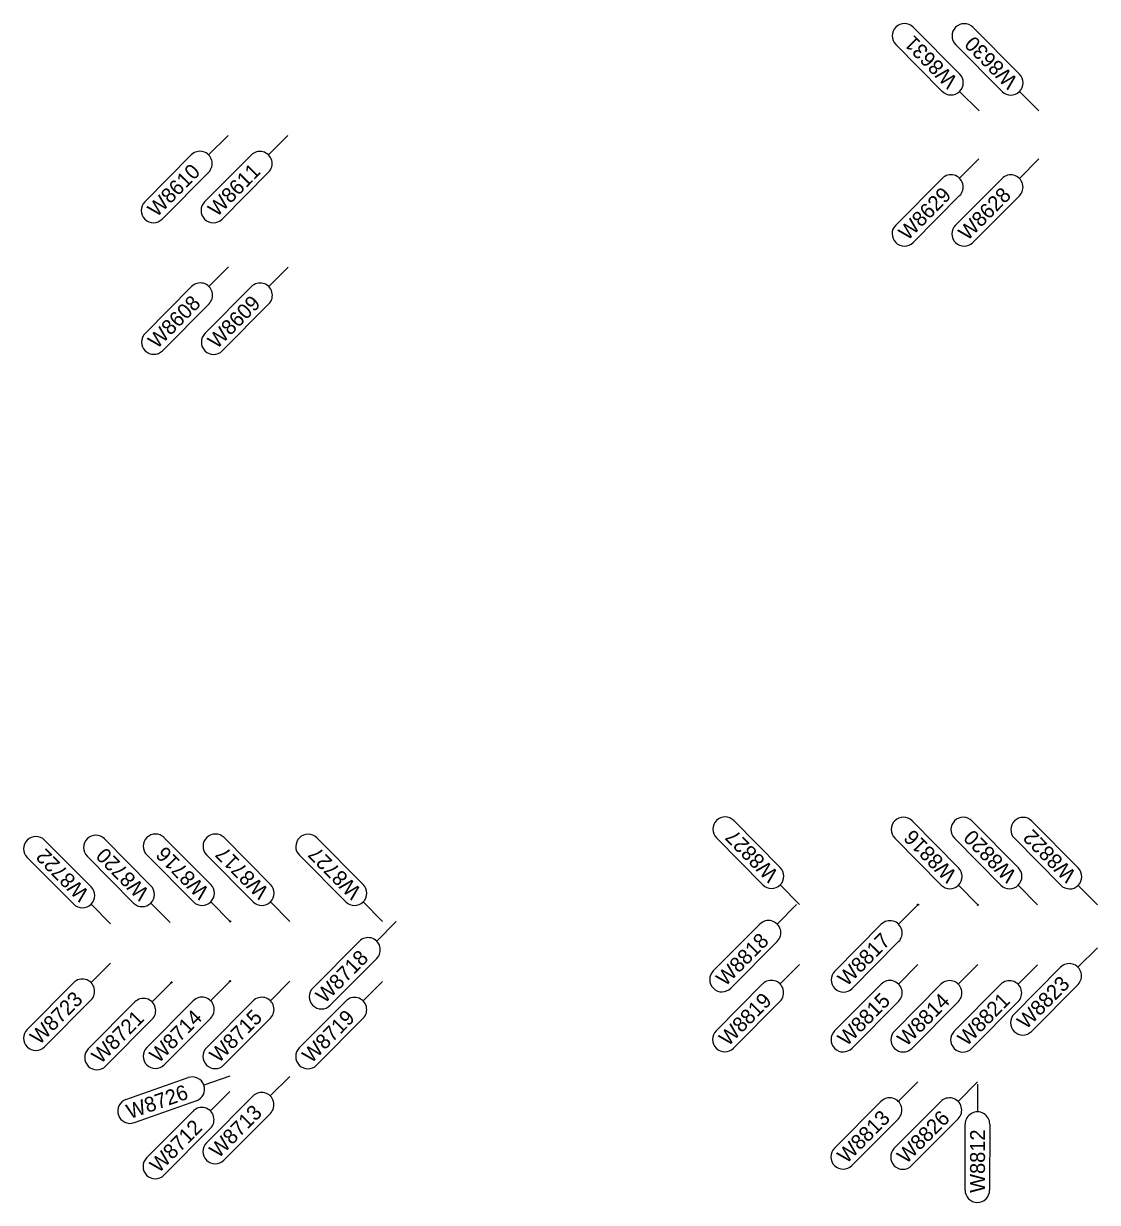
# Model space of a CAD drawing. Extents: x 12479652 to 12487250, y 9842710 to 9846560.
# Drawn here: x 12483660.6 to 12483750.4, y 9843527.9 to 9843626.5 of the extents above; entities that cross this region are included whole.
import ezdxf

# ---------------------------------------------------------------- set-up
doc = ezdxf.new("R2010")
doc.units = 0
doc.layers.add('_CIVIL_CONSTRUCTION', color=7, linetype='Continuous')
doc.layers.add('TextAlignmentLrg', color=7, linetype='Continuous')

msp = doc.modelspace()

# ---------------------------------------------------------------- linework, layer by layer
at = {"layer": '_CIVIL_CONSTRUCTION'}
for p, q in [((12483738.875, 9843622.237), (12483734.985, 9843626.15)), ((12483743.875, 9843622.229), (12483739.985, 9843626.142)), ((12483733.53, 9843624.703), (12483737.419, 9843620.79)), ((12483738.53, 9843624.696), (12483742.419, 9843620.783)), ((12483740.492, 9843619.155), (12483738.87, 9843620.786)), ((12483745.492, 9843619.147), (12483743.87, 9843620.778)), ((12483677.715, 9843617.112), (12483676.093, 9843615.481)), ((12483682.719, 9843617.104), (12483681.097, 9843615.473)), ((12483670.752, 9843611.564), (12483674.642, 9843615.476)), ((12483675.757, 9843611.556), (12483679.646, 9843615.469)), ((12483740.486, 9843615.155), (12483738.864, 9843613.523)), ((12483745.486, 9843615.147), (12483743.864, 9843613.516)), ((12483676.097, 9843614.03), (12483672.208, 9843610.117)), ((12483681.101, 9843614.022), (12483677.212, 9843610.109)), ((12483733.524, 9843609.606), (12483737.413, 9843613.519)), ((12483738.524, 9843609.599), (12483742.413, 9843613.511)), ((12483738.868, 9843612.072), (12483734.979, 9843608.16)), ((12483743.868, 9843612.065), (12483739.979, 9843608.152)), ((12483677.744, 9843606.112), (12483676.122, 9843604.481)), ((12483682.744, 9843606.104), (12483681.122, 9843604.473)), ((12483670.782, 9843600.563), (12483674.671, 9843604.476)), ((12483675.782, 9843600.556), (12483679.672, 9843604.469)), ((12483676.127, 9843603.03), (12483672.237, 9843599.117)), ((12483681.127, 9843603.022), (12483677.237, 9843599.109)), ((12483723.877, 9843555.921), (12483720, 9843559.845)), ((12483738.78, 9843555.901), (12483734.902, 9843559.826)), ((12483743.78, 9843555.894), (12483739.902, 9843559.818)), ((12483748.78, 9843555.886), (12483744.902, 9843559.811)), ((12483671.273, 9843554.403), (12483667.384, 9843558.317)), ((12483676.273, 9843554.506), (12483672.384, 9843558.419)), ((12483681.273, 9843554.509), (12483677.384, 9843558.422)), ((12483689.021, 9843554.497), (12483685.132, 9843558.41)), ((12483718.54, 9843558.403), (12483722.418, 9843554.479)), ((12483733.443, 9843558.384), (12483737.32, 9843554.459)), ((12483738.443, 9843558.376), (12483742.32, 9843554.451)), ((12483743.443, 9843558.368), (12483747.32, 9843554.444)), ((12483666.273, 9843554.301), (12483662.384, 9843558.214)), ((12483660.928, 9843556.768), (12483664.818, 9843552.854)), ((12483665.929, 9843556.87), (12483669.818, 9843552.957)), ((12483670.929, 9843556.973), (12483674.818, 9843553.06)), ((12483675.929, 9843556.976), (12483679.818, 9843553.063)), ((12483683.677, 9843556.964), (12483687.566, 9843553.051)), ((12483725.485, 9843552.834), (12483723.868, 9843554.47)), ((12483740.388, 9843552.814), (12483738.771, 9843554.45)), ((12483745.388, 9843552.806), (12483743.771, 9843554.443)), ((12483750.388, 9843552.799), (12483748.771, 9843554.435)), ((12483667.89, 9843551.219), (12483666.269, 9843552.85)), ((12483672.89, 9843551.321), (12483671.269, 9843552.953)), ((12483677.89, 9843551.424), (12483676.269, 9843553.055)), ((12483682.89, 9843551.427), (12483681.269, 9843553.058)), ((12483690.638, 9843551.415), (12483689.017, 9843553.046)), ((12483725.239, 9843552.829), (12483723.617, 9843551.198)), ((12483735.388, 9843552.813), (12483733.766, 9843551.182)), ((12483691.764, 9843551.403), (12483690.143, 9843549.771)), ((12483718.277, 9843547.281), (12483722.167, 9843551.193)), ((12483728.426, 9843547.265), (12483732.315, 9843551.178)), ((12483684.802, 9843545.854), (12483688.692, 9843549.767)), ((12483723.622, 9843549.747), (12483719.732, 9843545.834)), ((12483733.77, 9843549.731), (12483729.881, 9843545.819)), ((12483750.382, 9843549.226), (12483748.761, 9843547.595)), ((12483667.885, 9843547.938), (12483666.263, 9843546.307)), ((12483690.147, 9843548.321), (12483686.257, 9843544.408)), ((12483725.477, 9843547.829), (12483723.856, 9843546.197)), ((12483735.38, 9843547.813), (12483733.759, 9843546.182)), ((12483740.38, 9843547.806), (12483738.759, 9843546.175)), ((12483743.42, 9843543.678), (12483747.31, 9843547.59)), ((12483745.38, 9843547.798), (12483743.759, 9843546.167)), ((12483660.923, 9843542.39), (12483664.813, 9843546.302)), ((12483672.993, 9843546.322), (12483671.371, 9843544.691)), ((12483677.883, 9843546.424), (12483676.261, 9843544.793)), ((12483682.883, 9843546.416), (12483681.261, 9843544.785)), ((12483690.631, 9843546.404), (12483689.009, 9843544.773)), ((12483718.515, 9843542.28), (12483722.405, 9843546.193)), ((12483728.418, 9843542.265), (12483732.308, 9843546.178)), ((12483733.418, 9843542.257), (12483737.308, 9843546.17)), ((12483738.418, 9843542.25), (12483742.308, 9843546.163)), ((12483748.765, 9843546.144), (12483744.875, 9843542.231)), ((12483666.268, 9843544.856), (12483662.378, 9843540.943)), ((12483666.031, 9843540.774), (12483669.92, 9843544.687)), ((12483670.921, 9843540.875), (12483674.81, 9843544.788)), ((12483675.921, 9843540.868), (12483679.81, 9843544.781)), ((12483683.669, 9843540.856), (12483687.558, 9843544.769)), ((12483723.86, 9843544.746), (12483719.971, 9843540.834)), ((12483733.763, 9843544.731), (12483729.873, 9843540.819)), ((12483738.763, 9843544.724), (12483734.873, 9843540.811)), ((12483743.763, 9843544.716), (12483739.873, 9843540.803)), ((12483671.376, 9843543.24), (12483667.486, 9843539.327)), ((12483676.266, 9843543.342), (12483672.376, 9843539.429)), ((12483681.266, 9843543.334), (12483677.376, 9843539.421)), ((12483689.013, 9843543.322), (12483685.124, 9843539.409)), ((12483669.186, 9843536.538), (12483674.393, 9843538.364)), ((12483677.871, 9843538.497), (12483675.7, 9843537.735)), ((12483682.871, 9843538.463), (12483681.249, 9843536.832)), ((12483735.365, 9843538.013), (12483733.744, 9843536.382)), ((12483740.365, 9843538.005), (12483738.744, 9843536.374)), ((12483740.369, 9843537.806), (12483740.364, 9843535.505)), ((12483675.909, 9843532.915), (12483679.798, 9843536.827)), ((12483677.869, 9843537.212), (12483676.247, 9843535.581)), ((12483675.072, 9843536.428), (12483669.866, 9843534.601)), ((12483728.403, 9843532.465), (12483732.293, 9843536.377)), ((12483733.403, 9843532.457), (12483737.293, 9843536.37)), ((12483670.907, 9843531.663), (12483674.796, 9843535.576)), ((12483681.253, 9843535.381), (12483677.364, 9843531.468)), ((12483733.748, 9843534.931), (12483729.858, 9843531.018)), ((12483738.748, 9843534.923), (12483734.858, 9843531.01)), ((12483676.251, 9843534.13), (12483672.362, 9843530.217)), ((12483739.324, 9843528.965), (12483739.336, 9843534.482)), ((12483741.388, 9843534.477), (12483741.376, 9843528.96))]:
    msp.add_line(p, q, dxfattribs=at)
for centre, start, end in [((12483734.258, 9843625.427), 44.82528, 224.82528), ((12483739.258, 9843625.419), 44.82528, 224.82528), ((12483738.147, 9843621.514), 224.82528, 44.82528), ((12483743.147, 9843621.506), 224.82528, 44.82528), ((12483675.37, 9843614.753), 315.17021, 135.17022), ((12483680.374, 9843614.745), 315.17021, 135.17022), ((12483738.141, 9843612.796), 315.17021, 135.17022), ((12483743.141, 9843612.788), 315.17021, 135.17022), ((12483671.48, 9843610.84), 135.17022, 315.17021), ((12483676.484, 9843610.833), 135.17022, 315.17021), ((12483734.251, 9843608.883), 135.17022, 315.17021), ((12483739.251, 9843608.875), 135.17022, 315.17021), ((12483675.399, 9843603.753), 315.17021, 135.17022), ((12483680.399, 9843603.745), 315.17021, 135.17022), ((12483671.509, 9843599.84), 135.17022, 315.17021), ((12483676.51, 9843599.833), 135.17022, 315.17021), ((12483719.27, 9843559.124), 44.65528, 224.65528), ((12483734.172, 9843559.105), 44.65528, 224.65528), ((12483739.172, 9843559.097), 44.65528, 224.65528), ((12483744.172, 9843559.089), 44.65528, 224.65528), ((12483661.656, 9843557.491), 44.82528, 224.82528), ((12483666.656, 9843557.593), 44.82528, 224.82528), ((12483671.656, 9843557.696), 44.82528, 224.82528), ((12483676.656, 9843557.699), 44.82528, 224.82528), ((12483684.404, 9843557.687), 44.82528, 224.82528), ((12483723.147, 9843555.2), 224.65528, 44.65528), ((12483738.05, 9843555.18), 224.65528, 44.65528), ((12483743.05, 9843555.173), 224.65528, 44.65528), ((12483748.05, 9843555.165), 224.65528, 44.65528), ((12483670.546, 9843553.68), 224.82528, 44.82528), ((12483675.546, 9843553.783), 224.82528, 44.82528), ((12483680.546, 9843553.786), 224.82528, 44.82528), ((12483688.294, 9843553.774), 224.82528, 44.82528), ((12483665.545, 9843553.578), 224.82528, 44.82528), ((12483722.894, 9843550.47), 315.17021, 135.17022), ((12483733.043, 9843550.455), 315.17021, 135.17022), ((12483689.419, 9843549.044), 315.17021, 135.17022), ((12483748.037, 9843546.867), 315.17021, 135.17022), ((12483665.54, 9843545.579), 315.17021, 135.17022), ((12483719.005, 9843546.557), 135.17022, 315.17021), ((12483723.133, 9843545.47), 315.17021, 135.17022), ((12483729.153, 9843546.542), 135.17022, 315.17021), ((12483733.035, 9843545.455), 315.17021, 135.17022), ((12483738.035, 9843545.447), 315.17021, 135.17022), ((12483743.035, 9843545.439), 315.17021, 135.17022), ((12483685.53, 9843545.131), 135.17022, 315.17021), ((12483670.648, 9843543.963), 315.17021, 135.17022), ((12483675.538, 9843544.065), 315.17021, 135.17022), ((12483680.538, 9843544.057), 315.17021, 135.17022), ((12483688.286, 9843544.046), 315.17021, 135.17022), ((12483744.148, 9843542.954), 135.17022, 315.17021), ((12483661.651, 9843541.666), 135.17022, 315.17021), ((12483719.243, 9843541.557), 135.17022, 315.17021), ((12483729.146, 9843541.542), 135.17022, 315.17021), ((12483734.146, 9843541.534), 135.17022, 315.17021), ((12483739.146, 9843541.527), 135.17022, 315.17021), ((12483666.758, 9843540.051), 135.17022, 315.17021), ((12483671.648, 9843540.152), 135.17022, 315.17021), ((12483676.648, 9843540.145), 135.17022, 315.17021), ((12483684.396, 9843540.133), 135.17022, 315.17021), ((12483674.732, 9843537.396), 289.32919, 109.32919), ((12483680.526, 9843536.104), 315.17021, 135.17022), ((12483733.02, 9843535.654), 315.17021, 135.17022), ((12483738.02, 9843535.646), 315.17021, 135.17022), ((12483669.526, 9843535.57), 109.32919, 289.32919), ((12483675.524, 9843534.853), 315.17021, 135.17022), ((12483740.362, 9843534.48), 359.87469, 179.87469), ((12483676.636, 9843532.191), 135.17022, 315.17021), ((12483729.131, 9843531.741), 135.17022, 315.17021), ((12483734.131, 9843531.734), 135.17022, 315.17021), ((12483671.634, 9843530.94), 135.17022, 315.17021), ((12483740.35, 9843528.962), 179.87469, 359.87469)]:
    msp.add_arc(centre, 1.026, start, end, dxfattribs=at)
at = {"layer": 'TextAlignmentLrg'}
for centre in [(12483735.392, 9843552.818), (12483740.392, 9843552.81), (12483677.89, 9843551.424), (12483677.883, 9843546.424), (12483672.993, 9843546.322)]:
    msp.add_circle(centre, 0.05, dxfattribs=at)

# ---------------------------------------------------------------- texts
at = {"layer": '_CIVIL_CONSTRUCTION'}
for s, rotation, p in [('W8631', 134.82528, (12483738.762, 9843621.795)), ('W8630', 134.82528, (12483743.799, 9843621.751)), ('W8610', 45.17021, (12483671.751, 9843610.212)), ('W8611', 45.17021, (12483676.791, 9843610.241)), ('W8629', 45.17021, (12483734.524, 9843608.257)), ('W8628', 45.17021, (12483739.523, 9843608.248)), ('W8608', 45.17021, (12483671.781, 9843599.213)), ('W8609', 45.17021, (12483676.783, 9843599.206)), ('W8827', 134.65528, (12483723.788, 9843555.455)), ('W8816', 134.65528, (12483738.705, 9843555.421)), ('W8820', 134.65528, (12483743.703, 9843555.416)), ('W8822', 134.65528, (12483748.682, 9843555.429)), ('W8722', 134.82528, (12483666.177, 9843553.844)), ('W8720', 134.82528, (12483671.197, 9843553.925)), ('W8716', 134.82528, (12483676.2, 9843554.026)), ('W8717', 134.82528, (12483681.186, 9843554.043)), ('W8727', 134.82528, (12483688.934, 9843554.031)), ('W8817', 45.17021, (12483729.436, 9843545.925)), ('W8818', 45.17021, (12483719.277, 9843545.93)), ('W8718', 45.17021, (12483685.802, 9843544.504)), ('W8823', 45.17021, (12483744.427, 9843542.334)), ('W8723', 45.17021, (12483661.93, 9843541.046)), ('W8819', 45.17021, (12483719.516, 9843540.931)), ('W8815', 45.17021, (12483729.429, 9843540.926)), ('W8814', 45.17021, (12483734.41, 9843540.899)), ('W8821', 45.17021, (12483739.453, 9843540.935)), ('W8721', 45.17021, (12483667.066, 9843539.459)), ('W8714', 45.17021, (12483671.913, 9843539.517)), ('W8715', 45.17021, (12483676.932, 9843539.529)), ('W8719', 45.17021, (12483684.669, 9843539.506)), ('W8726', 19.32919, (12483669.493, 9843534.885)), ('W8713', 45.17021, (12483676.916, 9843531.571)), ('W8826', 45.17021, (12483734.4, 9843531.103)), ('W8712', 45.17021, (12483671.926, 9843530.333)), ('W8813', 45.17021, (12483729.41, 9843531.121)), ('W8812', 89.87469, (12483740.984, 9843528.736))]:
    msp.add_text(s, height=1.25, rotation=rotation, dxfattribs=at).set_placement(p)

doc.saveas('drawing.dxf')
